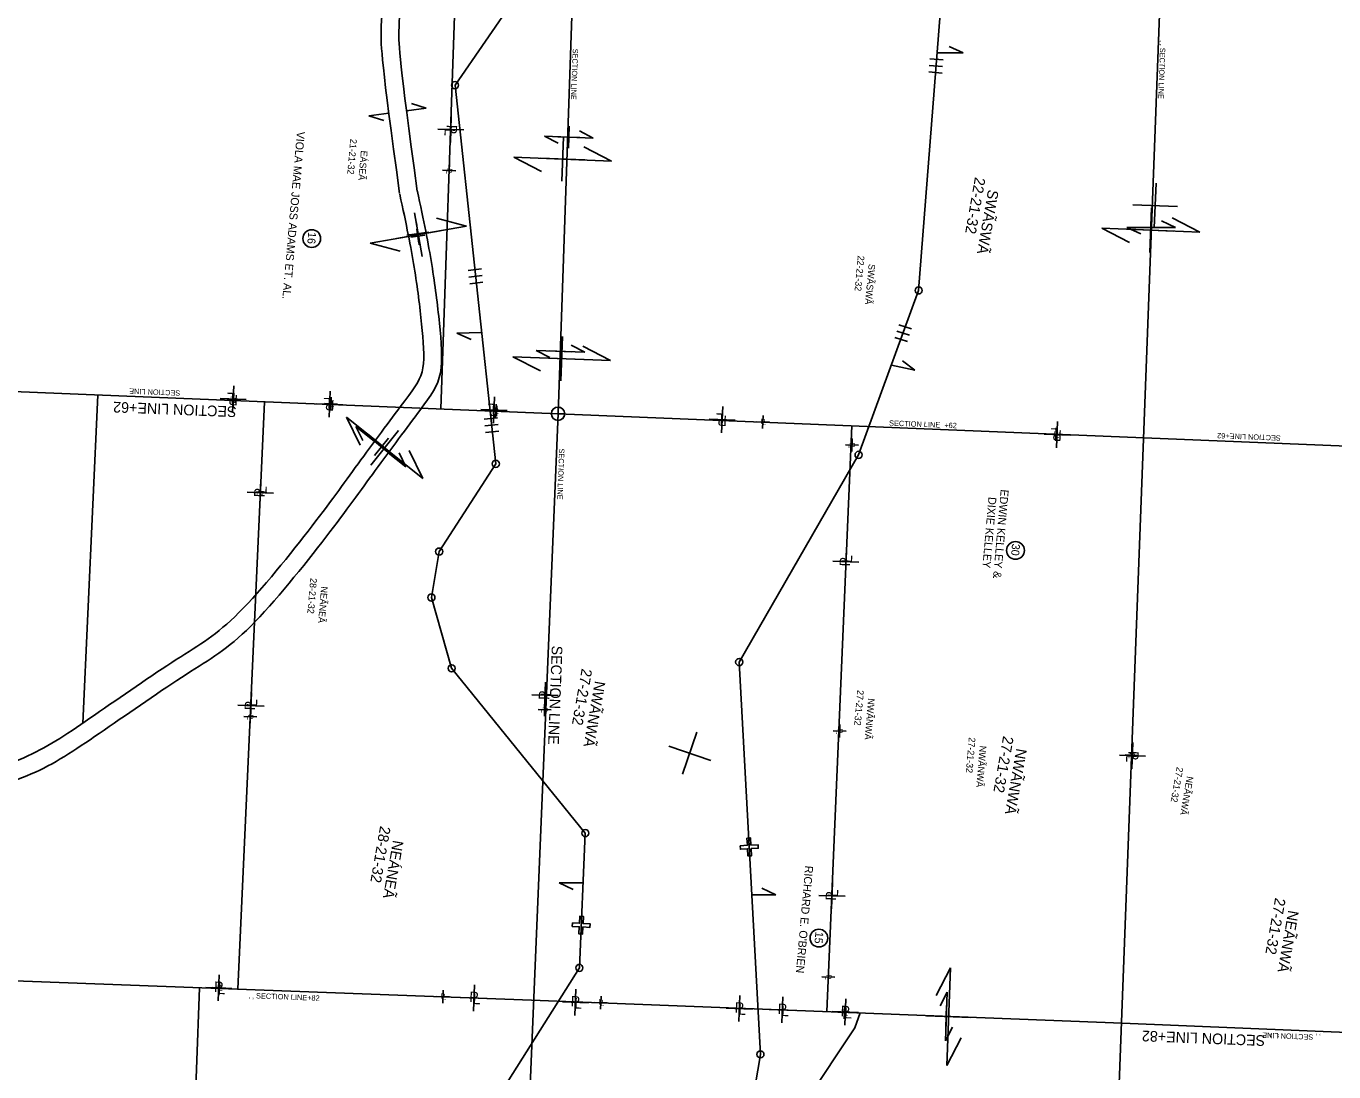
# Model space of a CAD drawing. Extents: x 2814293 to 2835768, y 121185 to 156337.
# Drawn here: x 2819450 to 2822390, y 129561 to 131914 of the extents above; entities that cross this region are included whole.
import ezdxf

# ---------------------------------------------------------------- set-up
doc = ezdxf.new("R2010")
doc.units = 0
for name, color, linetype in [('Default', 7, 'Continuous'), ('Photo-Retaining wall', 7, 'Continuous'), ('Roadway-Alignment notes', 7, 'Continuous'), ('Roadway-Ditches', 7, 'Continuous'), ('Roadway-Edge of pavement', 7, 'Continuous'), ('Roadway-Edge of shoulder', 7, 'Continuous'), ('Roadway-Entrances', 7, 'Continuous'), ('Roadway-New rw', 7, 'Continuous'), ('Roadway-Safety', 7, 'Continuous'), ('Roadway-Walls', 7, 'Continuous'), ('Scratch-2', 7, 'Continuous'), ('Scratch-4', 7, 'Continuous'), ('Scratch-5', 7, 'Continuous'), ('Text-New rw label', 7, 'Continuous'), ('Traffic_Control-Traffic barriers', 7, 'Continuous')]:
    doc.layers.add(name, color=color, linetype=linetype)

msp = doc.modelspace()

# ---------------------------------------------------------------- linework, layer by layer
at = {"layer": 'Default'}
for p, q in [((2821986.5, 131460.7), (2821990.4, 131560.7)), ((2822038.4, 131508.7), (2821938.5, 131512.6)), ((2820340.2, 131395.9), (2820323, 131494.5)), ((2820380.9, 131453.8), (2820282.4, 131436.6)), ((2820355.1, 131450.6), (2820305.5, 131444.1)), ((2820333.6, 131422.5), (2820327.1, 131472.1)), ((2820328.4, 131457.7), (2820332.8, 131426)), ((2820314.8, 131439.6), (2820346.5, 131444)), ((2820294.8, 130934), (2820217, 130996.9)), ((2820224.4, 130926.6), (2820287.3, 131004.4)), ((2820267.8, 130952), (2820228.9, 130983.4)), ((2820232.6, 130948.3), (2820264.1, 130987.2)), ((2820958, 130325.6), (2820925.7, 130230.9)), ((2820894.5, 130294.4), (2820989.2, 130262.1))]:
    msp.add_line(p, q, dxfattribs=at)
at = {"layer": 'Roadway-Ditches'}
for centre in [(2820091.8, 131436.3), (2821674.4, 130734.7), (2821232.3, 129862.4)]:
    msp.add_circle(centre, 20, dxfattribs=at)
at = {"layer": 'Roadway-Edge of pavement'}
for p, q in [((2820220.3, 131712.7), (2820265.2, 131718.6)), ((2820253.7, 131702.1), (2820220.3, 131712.7)), ((2820304.8, 131724), (2820349.2, 131729.8)), ((2820315.8, 131740.3), (2820349.2, 131729.8)), ((2820668.9, 131639.6), (2820670.8, 131689.6)), ((2820614.9, 131666.7), (2820724.8, 131662.5)), ((2820646, 131650.7), (2820614.9, 131666.7)), ((2820694.9, 131663.6), (2820644.9, 131665.6)), ((2820669.9, 131664.6), (2820669.9, 131664.6)), ((2820693.7, 131678.5), (2820724.8, 131662.5)), ((2821979.5, 131436.6), (2821979.5, 131486.6)), ((2821924.5, 131461.6), (2822034.5, 131461.6)), ((2821956.2, 131446.8), (2821924.5, 131461.6)), ((2822004.5, 131461.6), (2821954.5, 131461.6)), ((2821979.5, 131461.6), (2821979.5, 131461.6)), ((2822002.8, 131476.4), (2822034.5, 131461.6)), ((2820596.4, 131184.7), (2820706.3, 131180.5)), ((2820627.5, 131168.7), (2820596.4, 131184.7)), ((2820676.3, 131181.6), (2820626.4, 131183.6)), ((2820650.4, 131157.6), (2820652.3, 131207.6)), ((2820675.2, 131196.5), (2820706.3, 131180.5)), ((2820651.3, 131182.6), (2820651.3, 131182.6)), ((2820206.6, 130982.1), (2820191.2, 131013.5)), ((2820191.2, 131013.5), (2820232.9, 130979.8)), ((2820263.9, 130954.6), (2820303.6, 130922.5)), ((2820288.2, 130954), (2820303.6, 130922.5)), ((2821504.8, 129709.7), (2821520.7, 129740.9)), ((2821520.7, 129740.9), (2821516.8, 129630.9)), ((2821493.8, 129686.8), (2821543.7, 129685)), ((2821517.9, 129660.9), (2821519.6, 129710.9)), ((2821518.8, 129685.9), (2821518.8, 129685.9)), ((2821532.7, 129662.1), (2821516.8, 129630.9))]:
    msp.add_line(p, q, dxfattribs=at)
at = {"layer": 'Roadway-Edge of shoulder'}
for p, q in [((2820405.6, 131711.3), (2820403.6, 131652.4)), ((2820434, 131680.8), (2820375.2, 131682.9)), ((2819914, 131045.8), (2819916.3, 131104.7)), ((2819944.6, 131074.1), (2819885.7, 131076.4)), ((2820131.2, 131034.2), (2820133.5, 131093.1)), ((2820500.4, 131021.3), (2820502.7, 131080.2)), ((2820161.8, 131062.5), (2820102.9, 131064.8)), ((2820531, 131049.6), (2820472.1, 131051.9)), ((2821013.6, 130999.3), (2821015.9, 131058.2)), ((2821044.2, 131027.6), (2820985.3, 131029.9)), ((2821766.8, 130965.9), (2821769.1, 131024.7)), ((2821797.4, 130994.2), (2821738.5, 130996.4)), ((2819975.2, 130835.3), (2819977.3, 130894.2)), ((2819946.8, 130865.8), (2820005.7, 130863.7)), ((2821291.9, 130679.9), (2821294, 130738.8)), ((2821263.5, 130710.4), (2821322.4, 130708.3)), ((2820615.4, 130379.7), (2820617.5, 130438.5)), ((2819954.1, 130356.2), (2819956.1, 130415.1)), ((2820587, 130410.1), (2820645.9, 130408.1)), ((2819925.7, 130386.7), (2819984.5, 130384.6)), ((2821938.3, 130302.4), (2821936.3, 130243.6)), ((2821966.7, 130271.9), (2821907.9, 130274)), ((2821260.5, 129927.9), (2821262.6, 129986.8)), ((2821232.1, 129958.4), (2821291, 129956.4)), ((2819884, 129779.9), (2819881.7, 129721)), ((2819853.4, 129751.6), (2819912.3, 129749.3)), ((2820457.8, 129757.2), (2820455.6, 129698.3)), ((2820686, 129747.3), (2820683.7, 129688.4)), ((2820427.3, 129728.9), (2820486.1, 129726.6)), ((2820655.4, 129719), (2820714.2, 129716.8)), ((2821054.7, 129733.4), (2821052.4, 129674.5)), ((2821151.4, 129730.4), (2821149.1, 129671.5)), ((2821292.9, 129725.4), (2821290.6, 129666.5)), ((2821024.1, 129705.1), (2821083, 129702.8)), ((2821120.8, 129702.1), (2821179.7, 129699.8)), ((2821262.3, 129697.1), (2821321.2, 129694.8))]:
    msp.add_line(p, q, dxfattribs=at)
at = {"layer": 'Roadway-Entrances'}
for p, q in [((2820692.1, 132375.8), (2820645.7, 131042.3)), ((2822012.3, 132311.3), (2821962.5, 130985.5)), ((2821525.1, 131868.9), (2821556.8, 131854.1)), ((2821556.8, 131854.1), (2821497.9, 131854.1)), ((2815364.4, 131256.3), (2820645.7, 131042.3)), ((2820473.8, 131225), (2820418.1, 131223.6)), ((2820450.2, 131209.6), (2820418.1, 131223.6)), ((2820473.1, 131225), (2820473.1, 131225)), ((2821420.3, 131161.4), (2821448.1, 131140.1)), ((2821448.1, 131140.1), (2821395.3, 131151.9)), ((2820645.7, 131042.3), (2820536.2, 128412.4)), ((2823288.6, 130934), (2820645.7, 131042.3)), ((2821962.5, 130985.5), (2821862.4, 128356.1)), ((2820702.1, 129986.7), (2820648.3, 129986.7)), ((2820680, 129971.9), (2820648.3, 129986.7)), ((2821080.4, 129959.7), (2821080.4, 129959.7)), ((2821135.4, 129959.7), (2821081.5, 129959.7)), ((2821103.7, 129974.5), (2821135.4, 129959.7)), ((2818862.9, 129787.3), (2820585.7, 129723)), ((2820585.7, 129723), (2821914.4, 129670.7)), ((2821914.4, 129670.7), (2823240.9, 129616.7))]:
    msp.add_line(p, q, dxfattribs=at)
at = {"layer": 'Roadway-New rw'}
for p, q in [((2820414, 131781.5), (2820604.1, 132059.1)), ((2821510.5, 132016.9), (2821456.6, 131319.7)), ((2821481.6, 131841.1), (2821511.5, 131838.8)), ((2821479.4, 131811.2), (2821509.3, 131808.9)), ((2821480.5, 131826.1), (2821510.4, 131823.9)), ((2820414, 131781.5), (2820505.6, 130929.6)), ((2820443.5, 131364.6), (2820473.3, 131368.2)), ((2820445.3, 131349.7), (2820475.1, 131353.3)), ((2820447.1, 131334.8), (2820476.9, 131338.4)), ((2821456.6, 131319.7), (2821321.5, 130949.7)), ((2821412.4, 131242.6), (2821440.9, 131233.2)), ((2821403.1, 131214.1), (2821431.6, 131204.7)), ((2821407.8, 131228.3), (2821436.3, 131219)), ((2820479.7, 131030.1), (2820509.5, 131033.1)), ((2820481.2, 131015.2), (2820511.1, 131018.2)), ((2820482.7, 131000.2), (2820512.6, 131003.3)), ((2821053.2, 130483.5), (2821321.5, 130949.7)), ((2820378.4, 130732.1), (2820505.6, 130929.6)), ((2820361, 130628.8), (2820378.4, 130732.1)), ((2820406.4, 130469.5), (2820361, 130628.8)), ((2821053.2, 130483.5), (2821100.8, 129600.8)), ((2820707, 130098.7), (2820406.4, 130469.5)), ((2820693.7, 129795.4), (2820707, 130098.7)), ((2820498.4, 129486.1), (2820693.7, 129795.4)), ((2821016.2, 129106.2), (2821100.8, 129600.8))]:
    msp.add_line(p, q, dxfattribs=at)
for points in [[(2821055.5, 130070.3), (2821055.9, 130062.3), (2821071.9, 130063.3), (2821072.8, 130047.3), (2821080.8, 130047.7), (2821079.9, 130063.7), (2821095.9, 130064.6), (2821095.4, 130072.6), (2821079.4, 130071.7), (2821078.5, 130087.7), (2821070.5, 130087.2), (2821071.4, 130071.2), (2821055.5, 130070.3)], [(2820678, 129896.7), (2820677.6, 129888.7), (2820693.5, 129887.8), (2820692.7, 129871.8), (2820700.7, 129871.4), (2820701.5, 129887.4), (2820717.5, 129886.5), (2820717.9, 129894.5), (2820702, 129895.4), (2820702.8, 129911.3), (2820694.8, 129911.8), (2820694, 129895.8), (2820678, 129896.7)]]:
    msp.add_lwpolyline(points, close=True, dxfattribs=at)
for centre in [(2820505.6, 130929.6), (2821053.2, 130483.5)]:
    msp.add_circle(centre, 8.13, dxfattribs=at)
at = {"layer": 'Roadway-Walls'}
for p, q in [((2820401.4, 131604.2), (2820400.3, 131574.7)), ((2820415.6, 131588.9), (2820386.1, 131590)), ((2819930.8, 131072.9), (2819901.3, 131074.1)), ((2819915.5, 131058.8), (2819916.6, 131088.2)), ((2820135.5, 131079.2), (2820134.4, 131049.7)), ((2820120.2, 131065), (2820149.7, 131063.9)), ((2820491, 131050), (2820520.4, 131048.8)), ((2820506.3, 131064.1), (2820505.2, 131034.7)), ((2821106.9, 131038.5), (2821105.7, 131009.1)), ((2821091.6, 131024.4), (2821121, 131023.3)), ((2821766.2, 131010.5), (2821765, 130981.1)), ((2821307.1, 130986.5), (2821306, 130957.1)), ((2821750.9, 130996.4), (2821780.3, 130995.2)), ((2821321.3, 130971.3), (2821291.8, 130972.3)), ((2819991, 130864.2), (2819961.6, 130865.3)), ((2819976.8, 130879.5), (2819975.8, 130850)), ((2820616, 130391.3), (2820615, 130361.8)), ((2819968.2, 130360), (2819938.8, 130361)), ((2819954, 130375.2), (2819953, 130345.8)), ((2820630.2, 130376), (2820600.8, 130377.1)), ((2821279.6, 130343.2), (2821278.5, 130313.8)), ((2821293.8, 130327.9), (2821264.3, 130329)), ((2821950.6, 130273.4), (2821921.2, 130274.4)), ((2821936.4, 130288.6), (2821935.4, 130259.2)), ((2821268.4, 129774.5), (2821238.9, 129775.5)), ((2821254.2, 129789.7), (2821253.2, 129760.3)), ((2819869.4, 129751), (2819898.8, 129749.8)), ((2819884.7, 129765.1), (2819883.6, 129735.7)), ((2820387.6, 129745.4), (2820386.4, 129716)), ((2820372.3, 129731.3), (2820401.7, 129730.1)), ((2820727.1, 129717.8), (2820756.5, 129716.7)), ((2820742.4, 129732), (2820741.2, 129702.5)), ((2821275.1, 129695.9), (2821304.5, 129694.7)), ((2821290.3, 129710), (2821289.2, 129680.6))]:
    msp.add_line(p, q, dxfattribs=at)
at = {"layer": 'Scratch-2'}
for p, q in [((2820654, 131565.2), (2820657.8, 131665.1)), ((2820703.6, 131642.9), (2820765.8, 131610.9)), ((2820546, 131619.4), (2820765.8, 131610.9)), ((2820608.2, 131587.4), (2820546, 131619.4)), ((2820705.9, 131613.2), (2820605.9, 131617.1)), ((2820655.9, 131615.1), (2820655.9, 131615.1)), ((2820372.4, 131482.4), (2820440, 131464.1)), ((2821976.7, 131405.3), (2821980.6, 131505.3)), ((2822026.4, 131483.1), (2822088.6, 131451)), ((2820349.2, 131448.3), (2820440, 131464.1)), ((2821868.8, 131459.6), (2822088.6, 131451)), ((2821931, 131427.5), (2821868.8, 131459.6)), ((2822028.6, 131453.4), (2821928.7, 131457.2)), ((2821978.7, 131455.3), (2821978.7, 131455.3)), ((2820223.3, 131426.3), (2820309.6, 131441.4)), ((2820290.8, 131408), (2820223.3, 131426.3)), ((2820652.2, 131116.4), (2820656, 131216.3)), ((2820701.8, 131194.1), (2820764, 131162.1)), ((2820544.2, 131170.6), (2820764, 131162.1)), ((2820606.4, 131138.6), (2820544.2, 131170.6)), ((2820704.1, 131164.4), (2820604.1, 131168.3)), ((2820654.1, 131166.4), (2820654.1, 131166.4)), ((2820201.1, 130971.7), (2820170.3, 131034.6)), ((2820170.3, 131034.6), (2820234.8, 130982.5)), ((2820255.9, 130965.5), (2820255.9, 130965.5)), ((2820266, 130957.3), (2820341.4, 130896.3)), ((2820310.7, 130959.2), (2820341.4, 130896.3)), ((2821496.1, 129733.1), (2821527.9, 129795.4)), ((2821527.9, 129795.4), (2821520.1, 129575.6)), ((2821522.3, 129635.5), (2821525.8, 129735.5)), ((2821474.1, 129687.3), (2821574, 129683.7)), ((2821524, 129685.5), (2821524, 129685.5)), ((2821552, 129637.9), (2821520.1, 129575.6))]:
    msp.add_line(p, q, dxfattribs=at)
at = {"layer": 'Scratch-4'}
for p, q in [((2820630.7, 131042.8), (2820645.7, 131042.3)), ((2820645.7, 131042.3), (2820645.2, 131027.3)), ((2820645.7, 131042.3), (2820646.2, 131057.3)), ((2820660.7, 131041.8), (2820645.7, 131042.3))]:
    msp.add_line(p, q, dxfattribs=at)
msp.add_circle((2820645.7, 131042.3), 15, dxfattribs=at)
for start, end in [(88.1, 178.1), (268.1, 358.1)]:
    msp.add_arc((2820645.7, 131042.3), 15, start, end, dxfattribs=at)
at = {"layer": 'Text-New rw label'}
for centre in [(2820414, 131781.5), (2821456.6, 131319.7), (2821321.5, 130949.7), (2820378.4, 130732.1), (2820361, 130628.8), (2820406.4, 130469.5), (2820707, 130098.7), (2820693.7, 129795.4), (2821100.8, 129600.8)]:
    msp.add_circle(centre, 8, dxfattribs=at)
at = {"layer": 'Traffic_Control-Traffic barriers'}
for p, q in [((2820423.2, 132238.8), (2820381.9, 131053)), ((2819577.3, 130346.3), (2819610.8, 131084.2)), ((2819985.5, 131069), (2819925.4, 129747.7)), ((2821306.4, 131015.2), (2821250, 129696.9)), ((2821325.3, 129693.9), (2821312.8, 129660.4)), ((2821312.8, 129660.4), (2821082.9, 129314.5))]:
    msp.add_line(p, q, dxfattribs=at)
msp.add_lwpolyline([(2819839.7, 129750.8), (2819819.2, 129201.2), (2819798.3, 128353.8)], dxfattribs=at)
for points in [[(2820289.4, 131538), (2820248.4, 131835.6), (2820245.9, 131907.1), (2820253.9, 131990.2), (2820268.9, 132068.3), (2820290.8, 132135), (2820315.3, 132190.2), (2820334.7, 132232.6), (2820344.9, 132254.7)], [(2820329, 131543.4), (2820288.3, 131839), (2820286, 131905.9), (2820293.5, 131984.5), (2820307.7, 132058.2), (2820328.2, 132120.6), (2820352.8, 132176.2), (2820373.7, 132221.8), (2820385.2, 132246.5)], [(2818787.1, 128593.2), (2818789.2, 128610.4), (2818801, 128699.9), (2818831.4, 128865.4), (2818867.8, 129199.8), (2818876.3, 129324.7), (2818898.3, 129421.6), (2818849.4, 129639.4), (2818839.1, 129653.4), (2818819.7, 129750.6), (2818972.3, 129919), (2819007.2, 129963.4), (2819027.6, 130013.6), (2819053.1, 130078.1), (2819201.8, 130156.7), (2819261.5, 130171.2), (2819306.5, 130181.7), (2819476.3, 130228.2), (2819611.7, 130321.2), (2819826.5, 130470.1), (2819939.3, 130532.3), (2820143.5, 130786.8), (2820228.9, 130908.5), (2820347.4, 131066), (2820389.8, 131123.7), (2820379.9, 131244.4), (2820364.1, 131374.7), (2820344, 131475.4), (2820328.8, 131545)], [(2818837.6, 129821.5), (2818863.6, 129858.7), (2818944.9, 129948.8), (2818972.2, 129983.6), (2818990.5, 130028.5), (2819021.4, 130106.6), (2819187.5, 130194.4), (2819252.2, 130210.1), (2819296.7, 130220.4), (2819459.2, 130265), (2819588.9, 130354.2), (2819805.4, 130504.2), (2819913.1, 130563.5), (2820111.5, 130810.8), (2820196.6, 130932.1), (2820315.3, 131089.9), (2820348.8, 131135.3), (2820340.1, 131240.3), (2820324.6, 131368.4), (2820304.8, 131467.2), (2820289.7, 131536.4)]]:
    msp.add_open_spline(points, degree=3, dxfattribs=at)

# ---------------------------------------------------------------- texts
at = {"layer": 'Photo-Retaining wall'}
for s, rotation, p in [('21-21-32', 265.038, (2820178.6, 131661.2)), ('EÁSEÃ', 265.038, (2820202.5, 131634.9)), ('22-21-32', 264.738, (2821319.9, 131398.6)), ('SWÃSWÃ', 264.738, (2821344.3, 131379.7)), ('28-21-32', 265.038, (2820088.8, 130673)), ('NEÃNEÃ', 265.038, (2820113.2, 130654.2)), ('27-21-32', 265.038, (2821318.6, 130421.2)), ('NWÃNWÃ', 265.038, (2821343, 130402.5)), ('27-21-32', 265.038, (2821569.6, 130314.5)), ('NWÃNWÃ', 265.038, (2821594.1, 130295.7)), ('27-21-32', 260.038, (2822037.1, 130248.2)), ('NEÃNWÃ', 260.038, (2822059.8, 130227.4))]:
    msp.add_text(s, height=15, rotation=rotation, dxfattribs=at).set_placement(p)
at = {"layer": 'Roadway-Alignment notes'}
for s, p in [('22-21-32', (2821583.4, 131575.6)), ('SWÃSWÃ', (2821613, 131547.7)), ('27-21-32', (2820699.1, 130470)), ('NWÃNWÃ', (2820728.7, 130442.1)), ('27-21-32', (2821646.8, 130318.2)), ('NWÃNWÃ', (2821676.4, 130290.3)), ('28-21-32', (2820245.8, 130115.7)), ('NEÁNEÃ', (2820274.7, 130083.7)), ('27-21-32', (2822258.4, 129954.1)), ('NEÃNWÃ', (2822288, 129926.1))]:
    msp.add_text(s, height=24, rotation=260.038, dxfattribs=at).set_placement(p)
at = {"layer": 'Roadway-Ditches'}
for s, p in [('VIOLA MAE JOSS ADAMS ET. AL.', (2820058.5, 131677.8)), ('16', (2820084.1, 131451.7)), ('EDWIN KELLEY &', (2821641.3, 130872.5)), ('DIXIE KELLEY', (2821613.8, 130855.5)), ('30', (2821666.8, 130750.4)), ("RICHARD E. O'BRIEN", (2821201.6, 130025.9)), ('15', (2821224.6, 129877.4))]:
    msp.add_text(s, height=18, rotation=265.038, dxfattribs=at).set_placement(p)
at = {"layer": 'Roadway-Edge of shoulder'}
for s, rotation, p in [('P', 267.9775, (2820395.4, 131692.8)), ('L', 267.9775, (2820390.8, 131685)), ('L', 177.7804, (2819918.4, 131089.1)), ('P', 177.7804, (2819926.2, 131084.5)), ('L', 177.7804, (2820135.6, 131077.4)), ('P', 177.7804, (2820143.4, 131072.8)), ('L', 177.7804, (2820504.8, 131064.6)), ('P', 177.7804, (2820512.6, 131060)), ('L', 177.7804, (2821017.9, 131042.6)), ('P', 177.7804, (2821025.8, 131038)), ('L', 177.7804, (2821771.1, 131009.1)), ('P', 177.7804, (2821779, 131004.5)), ('P', 87.9775, (2819985.5, 130853.7)), ('L', 87.9775, (2819990.1, 130861.6)), ('P', 87.9775, (2821302.2, 130698.3)), ('L', 87.9775, (2821306.8, 130706.2)), ('L', 87.9775, (2820630.3, 130405.9)), ('P', 87.9775, (2819964.3, 130374.6)), ('L', 87.9775, (2819968.9, 130382.5)), ('P', 87.9775, (2820625.7, 130398.1)), ('L', 267.9775, (2821923.5, 130276.2)), ('P', 267.9775, (2821928.1, 130284)), ('P', 87.9775, (2821270.8, 129946.4)), ('L', 87.9775, (2821275.3, 129954.2)), ('P', 357.7804, (2819871.8, 129741.3)), ('L', 357.7804, (2819879.6, 129736.7)), ('P', 357.7804, (2820445.7, 129718.6)), ('L', 357.7804, (2820453.5, 129714)), ('P', 357.7804, (2820673.8, 129708.7)), ('L', 357.7804, (2820681.6, 129704.1)), ('P', 357.7804, (2821042.5, 129694.7)), ('L', 357.7804, (2821050.4, 129690.1)), ('P', 357.7804, (2821139.2, 129691.7)), ('L', 357.7804, (2821147, 129687.1)), ('P', 357.7804, (2821280.7, 129686.8)), ('L', 357.7804, (2821288.6, 129682.1))]:
    msp.add_text(s, height=23.6, rotation=rotation, dxfattribs=at).set_placement(p)
at = {"layer": 'Roadway-Safety'}
for s, rotation, p in [('SECTION LINE', 267.8429, (2820678.9, 131863.8)), ('‚ ‚ SECTION LINE', 267.9775, (2822000, 131882.5)), ('SECTION LINE', 177.7804, (2819796.5, 131094.7)), ('SECTION LINE  +62', 357.7804, (2821389.9, 131015.5)), ('SECTION LINE+62', 177.7804, (2822271.2, 130993.5)), ('SECTION LINE', 267.8429, (2820648.2, 130964.2)), ('‚ ‚ SECTION LINE+82', 357.7804, (2819949.8, 129727.4)), ('‚ ‚ SECTION LINE', 177.7804, (2822360.9, 129644.9))]:
    msp.add_text(s, height=12, rotation=rotation, dxfattribs=at).set_placement(p)
at = {"layer": 'Roadway-Walls'}
for s, rotation, p in [('L', 267.9775, (2820394, 131591)), ('P', 267.9775, (2820396.2, 131594.9)), ('L', 177.7804, (2819917.7, 131080.4)), ('P', 177.7804, (2819921.6, 131078.1)), ('P', 357.7804, (2820129.4, 131059.9)), ('L', 357.7804, (2820133.4, 131057.6)), ('P', 357.7804, (2820500.2, 131044.8)), ('L', 357.7804, (2820504.1, 131042.5)), ('P', 357.7804, (2821100.8, 131019.2)), ('L', 357.7804, (2821104.7, 131016.9)), ('P', 357.7804, (2821760.1, 130991.2)), ('L', 357.7804, (2821764, 130988.9)), ('L', 267.9775, (2821299.6, 130973.4)), ('P', 267.9775, (2821301.9, 130977.3)), ('L', 267.9775, (2819969.4, 130866.3)), ('P', 267.9775, (2819971.7, 130870.3)), ('L', 267.9775, (2819946.6, 130362.1)), ('P', 267.9775, (2819948.9, 130366)), ('L', 267.9775, (2820608.6, 130378.1)), ('P', 267.9775, (2820610.9, 130382)), ('P', 267.9775, (2821274.4, 130334)), ('L', 267.9775, (2821272.1, 130330.1)), ('L', 267.9775, (2821929, 130275.5)), ('P', 267.9775, (2821931.3, 130279.4)), ('L', 267.9775, (2821246.8, 129776.6)), ('P', 267.9775, (2821249, 129780.5)), ('P', 357.7804, (2819878.6, 129745.8)), ('L', 357.7804, (2819882.5, 129743.5)), ('P', 357.7804, (2820381.5, 129726.1)), ('L', 357.7804, (2820385.4, 129723.8)), ('P', 357.7804, (2820736.3, 129712.6)), ('L', 357.7804, (2820740.2, 129710.3)), ('P', 357.7804, (2821284.3, 129690.7)), ('L', 357.7804, (2821288.2, 129688.4))]:
    msp.add_text(s, height=11.8, rotation=rotation, dxfattribs=at).set_placement(p)
at = {"layer": 'Scratch-5'}
for s, rotation, p in [('SECTION LINE+62', 177.7804, (2819923, 131058.5)), ('SECTION LINE', 267.8429, (2820631.8, 130520.9)), ('‚ ‚ SECTION LINE+82', 177.7804, (2822268.4, 129642.3))]:
    msp.add_text(s, height=24, rotation=rotation, dxfattribs=at).set_placement(p)

doc.saveas('drawing.dxf')
